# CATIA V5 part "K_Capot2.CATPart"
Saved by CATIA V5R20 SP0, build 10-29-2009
Part number: Capot2
Bounding box of the stored display mesh (mm): x -33.5 to -30.5, y -29.999 to 229.999, z -30 to 80
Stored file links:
  G:\Khaled_CFAO_2011\SIL\SIL_GR1\mneves\Khaled\CAD_CATIA_Modifie\K_Capot2.CATPart
  G:\Khaled_CFAO_2011\SIL\SIL_GR1\mneves\Khaled\CAD_CATIA_Modifie\K_AssPince_A_Bois.CATProduct
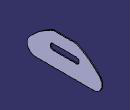
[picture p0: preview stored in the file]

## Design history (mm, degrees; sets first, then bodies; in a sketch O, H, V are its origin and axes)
External parameters (linked from other documents)
  External.Distance_Inter_Pivot = 200 mm
  External.Epaisseur_Cloison = 3 mm
Set1
  Plane1 "Plan_Capot2": linked copy from another document
  Point1 "Centre_Pivot_Support2": linked copy from another document
  Point2 "Centre_Pivot_Support1": linked copy from another document
  Line1: linked copy from another document
Body1 (main body)
  Sketch1 on Plane1, origin (-30.5, 0, 0), H (0, 1, 0), V (0, 0, 1)
    line L1 (0, -30) -> (200, -30)
    point P1 (0, -30)
    arc A1 centre (200, 0) radius 30 from (200, -30) to (222.2183, 20.158) ccw
    point P3 (200, 0)
    reference projected point E1 (200, 0) from Point1
    arc A2 centre (0, 0) radius 30 from (-22.2183, 20.158) to (0, -30) ccw
    point P4 (0, 0)
    reference projected point E2 (0, 0) from Point2
    reference projected line E3 (0, 0) -> (200, 0) from Line1
    line L2 (140, 80) -> (60, 80)
    point P5 (140, 80)
    point P6 (60, 80)
    reference projected point E4 (200, 0) from Point1
    reference projected point E5 (0, 0) from Point2
    point P7 (60, 80)
    arc A3 centre (162.9342, -147.8257) radius 250 from (60, 80) to (-22.2183, 20.158) ccw
    point P11 (140, 80)
    arc A4 centre (37.0658, -147.8257) radius 250 from (140, 80) to (222.2183, 20.158) cw
    construction line L3 (140.4648, 30) -> (59.5352, 30)
    point P13 (140.4648, 30)
    point P14 (59.5352, 30)
    line L4 (140.4648, 20) -> (59.5352, 20)
    line L5 (59.5352, 40) -> (140.4648, 40)
    arc A5 centre (59.5352, 30) radius 10 from (59.5352, 20) to (59.5352, 40) cw
    arc A6 centre (140.4648, 30) radius 10 from (140.4648, 40) to (140.4648, 20) cw
    reference projected point E6 (0, 0) from Point2
    reference projected point E7 (200, 0) from Point1
    distance E3 L1 = 30 {= External.Distance_Inter_Pivot /8+External.Distance_Inter_Pivot /40}
    distance P5 E4 = 100 {= External.Distance_Inter_Pivot /2}
    distance E5 P6 = 100 {= External.Distance_Inter_Pivot /2}
    radius A3 = 250 {= External.Distance_Inter_Pivot *5/4}
    length L2 = 80 {= External.Distance_Inter_Pivot /2.5}
    radius A4 = 250 {= External.Distance_Inter_Pivot *5/4}
    distance L1 L4 = 50 {= External.Distance_Inter_Pivot /4}
    distance P14 E6 = 66.6667 {= External.Distance_Inter_Pivot /3}
    distance P13 E7 = 66.6667 {= External.Distance_Inter_Pivot /3}
    coincidence: P1 V, P3 E1, P4 E2, P7 P6, P11 P5
    horizontal: L1 H, L2 H
    tangency: L1 A1, A2 L1, A3 A2, A1 A4, L3 A2, A5 L4, A6 L4, A5 L5, A6 L5
    parallelism: L3 L4
  Pad1: profile Sketch1, direction (-1, 0, 0), length 3 {= External.Epaisseur_Cloison}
